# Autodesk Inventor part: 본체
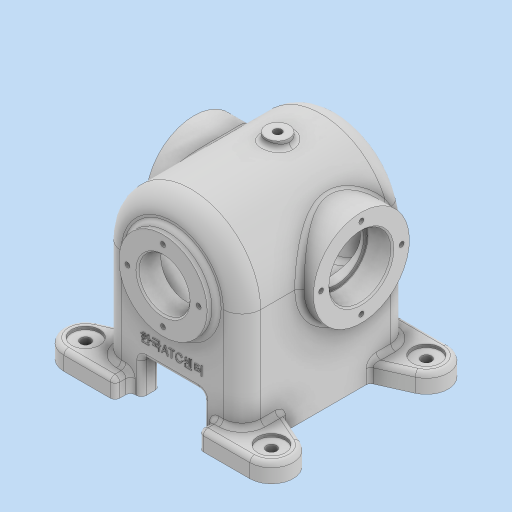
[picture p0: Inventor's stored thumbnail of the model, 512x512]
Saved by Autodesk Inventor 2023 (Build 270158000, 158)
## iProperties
Created: 2024-09
Part Number: 본체
Material: 일반
Document SubType Name: Modeling
Designer: asung
Density: 1 g/cm^3
Appearance: 기본값
Author: asung
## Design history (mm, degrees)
sketch "스케치1"
  geometry: L1 (-45, 0)-(45, 0); L2 (45, 0)-(45, -76); L3 (45, -76)-(-45, -76); L4 (-45, -76)-(-45, 0); L5 (-45, 0)-(45, -76); L6 (45, 0)-(-45, -76); L7 (-20, -53)-(20, -53); L8 (20, -53)-(20, -76); L9 (20, -76)-(-20, -76); L10 (-20, -76)-(-20, -53); L11 (-20, -53)-(20, -76); L12 (20, -53)-(-20, -76); C1 r 45 at (0, 0); 9 further points
  constraints: 24 end point, 7 midpoint, 4 parallel, 2 coincident, 2 horizontal, 2 perpendicular, 1 centre point
  dimensions: "d0" = 90 diameter of C1; "d2" = 90 distance of L2.end L3.end; "d3" = 76 distance of L1.end L2.end; "d4" = 40 distance of L8.end L9.end; "d5" = 23 distance of L7.end L8.end
extrude "돌출1" new body sketch "스케치1" stored distance "d6" = 108; taper "d7" = 0 deg
sketch "스케치2"
  geometry: C1 r 28.5 at (0, 0); 1 further point
  constraints: 1 centre point, 1 coincident
  dimensions: "d8" = 57 diameter of C1
extrude "돌출2" join sketch "스케치2" distance "d9" = 6; taper "d10" = 0 deg
node "작업 평면2"
sketch "스케치3"
  geometry: L1 (28.5, 60)-(-28.5, 60) reference; C1 r 31 at (0, -14); 2 further points
  constraints: 1 centre point, 1 midpoint, 1 vertical alignment
  dimensions: "d80" = 62 diameter of C1; "d81" = 74 distance from line of L1 C1.centre
extrude "돌출3" join sketch "스케치3" stored distance "d13" = 6; taper "d14" = 0 deg
sketch "스케치6"
  geometry: L1 (-28.5, 54)-(-28.5, 60) reference; L2 (-28.5, 60)-(28.5, 60) reference; L3 (28.5, 60)-(28.5, 54) reference; L4 (28.5, 54)-(45, 54) reference; L5 (45, 54)-(45, -54) reference; L6 (45, -54)-(-53, -54) reference; L7 (-53, -54)-(-53, 54) reference; L8 (-53, 54)-(-28.5, 54) reference; L9 (0, -54)-(0, 54) reference; L10 (0, -54)-(0, 60); L11 (28.5, 60)-(-28.5, 60) reference; L12 (0, -45)-(33, -45); L13 (36, -42)-(36, 42); L14 (33, 45)-(0, 45); L15 (0, 45)-(0, -45); A1 r 3 centre (33, -42) between (33, -45) and (36, -42); A2 r 3 centre (33, 42) between (36, 42) and (33, 45); 5 further points
  constraints: 10 end point, 4 point on circle, 4 tangent, 2 centre point, 2 parallel, 1 equal radius, 1 horizontal, 1 midpoint, 1 perpendicular, 1 point on line
  dimensions: "d29" = 9 distance between parallel lines of L13 L5; "d30" = 9 distance between parallel lines of L12 L6; "d31" = 9 distance between parallel lines of L4 L14; "d32" = 3 radius of A1
revolve "회전1" sketch "스케치6" stored, may be unused: angle "d33" = 90 deg
sketch "스케치7"
  geometry: C1 r 28.5 at (0, 0) reference; 2 further points
  constraints: 1 coincident
hole "구멍3" sketch "스케치7" at (0, 0) diameter "d34" = 33; stored, may be unused: countersink angle "d38" = 90 deg, drill point angle "d40" = 118 deg; dims "d35" = 6, "d36" = 40, "d37" = 16, "d39" = 60
chamfer "모따기1" distance "d41" = 1; stored, may be unused: second distance "d42" = 2, angle "d43" = 45 deg
fillet "모깎기1" dims "d44" = 12
node "작업 평면3"
sketch "스케치11" dims "d69" = 46
  geometry: C1 r 16.5 at (0, 0) reference; 3 further points
  constraints: 2 vertical alignment, 1 coincident, 2 other
hole "구멍6" sketch "스케치11" at (0, 23) diameter "d70" = 3.242; stored, may be unused: countersink angle "d74" = 90 deg, drill point angle "d76" = 118 deg; dims "d71" = 8, "d72" = 4, "d73" = 2, "d75" = 10
sketch "스케치12"
  geometry: C1 r 31 at (0, 0) reference; 2 further points
  constraints: 1 coincident
hole "구멍7" sketch "스케치12" at (0, 0) diameter "d82" = 35; stored, may be unused: countersink angle "d86" = 90 deg, drill point angle "d88" = 118 deg; dims "d83" = 8, "d84" = 40, "d85" = 16, "d87" = 100
sketch "스케치13"
  geometry: C1 r 31 at (0, 0) reference; 2 further points
  constraints: 1 coincident
hole "구멍8" sketch "스케치13" at (0, 0) diameter "d89" = 35; stored, may be unused: countersink angle "d93" = 90 deg, drill point angle "d95" = 118 deg; dims "d90" = 6, "d91" = 40, "d92" = 16, "d94" = 100
chamfer "모따기2" distance "d96" = 1; stored, may be unused: second distance "d97" = 2, angle "d98" = 45 deg
fillet "모깎기4" dims "d99" = 0.3
fillet "모깎기5" dims "d100" = 3
node "작업 평면5"
sketch "스케치14"
  geometry: L1 (48.5, 114)-(-8.5, 114) reference; L2 (74, 9)-(74, 71) reference; C1 r 7.5 at (20, 40); 2 further points
  constraints: 1 centre point, 1 midpoint, 1 vertical alignment
  dimensions: "d102" = 15 diameter of C1; "d103" = 74 distance from line of L1 C1.centre
extrude "돌출5" join sketch "스케치14" stored distance "d104" = 10; taper "d105" = 0 deg
fillet "모깎기6" dims "d110" = 3
sketch "스케치16"
  geometry: C1 r 7.5 at (0, 0) reference; 2 further points
  constraints: 1 coincident
hole "구멍9" sketch "스케치16" at (0, 0) diameter "d111" = 5.1881; stored, may be unused: countersink angle "d115" = 90 deg, drill point angle "d117" = 118 deg; dims "d112" = 20, "d113" = 40, "d114" = 16, "d116" = 21
sketch "스케치18" dims "d125" = 52
  geometry: C1 r 31 at (0, 0) reference; C2 r 21 at (0, 0) reference; 3 further points
  constraints: 2 vertical alignment, 1 coincident, 2 other
hole "구멍11" sketch "스케치18" at (0, 26) diameter "d126" = 3.242; stored, may be unused: countersink angle "d130" = 90 deg, drill point angle "d132" = 118 deg; dims "d127" = 8, "d128" = 4, "d129" = 2, "d131" = 10
sketch "스케치19"
  geometry: L1 (0, 0)-(-13, 0) reference; L2 (0, 0)-(0, 108) reference; L3 (-13, 108)-(0, 108) reference; L4 (-25, 96)-(-25, 12) reference; L5 (65, 12)-(65, 96) reference; L6 (40, 108)-(53, 108) reference; L7 (40, 0)-(40, 108) reference; L8 (53, 0)-(40, 0) reference; L9 (-40, -10)-(-7, -10); L10 (-7, -10)-(-7, 0); L11 (-25, 26)-(-45.693, 16.79); L12 (-25, 54)-(65, 54); L13 (18.379, 114)-(21.621, 114) reference; L14 (40, 0)-(0, 0) reference; L15 (20, 0)-(20, 108); L16 (0, 108)-(40, 108) reference; L17 (20, 114)-(20, 108); L18 (21.621, 104)-(21.621, 114) reference; L19 (-7, 118)-(-7, 108); L20 (-40, 118)-(-7, 118); L21 (-25, 82)-(-45.693, 91.21); L22 (47, -10)-(47, 0); L23 (80, -10)-(47, -10); L24 (65, 26)-(85.693, 16.79); L25 (65, 82)-(85.693, 91.21); L26 (80, 118)-(47, 118); L27 (47, 118)-(47, 108); A1 r 12 centre (-13, 12) between (-25, 12) and (-13, 0) reference; A2 r 12 centre (-13, 96) between (-13, 108) and (-25, 96) reference; A3 r 12 centre (53, 12) between (53, 0) and (65, 12) reference; A4 r 12 centre (53, 96) between (65, 96) and (53, 108) reference; A5 r 14 centre (-40, 4) between (-40, -10) and (-45.693, 16.79); A6 r 14 centre (-40, 104) between (-40, 118) and (-45.693, 91.21); A7 r 14 centre (80, 4) between (80, -10) and (85.693, 16.79); A8 r 14 centre (80, 104) between (80, 118) and (85.693, 91.21); 7 further points
  constraints: 30 end point, 18 symmetric about line, 8 point on circle, 5 midpoint, 4 centre point, 2 point on line, 2 tangent, 1 horizontal, 1 parallel, 1 perpendicular, 3 other
  dimensions: "d136" = 28 diameter of A5; "d137" = 60 horizontal distance of point (20, 54) A5.centre; "d138" = 18 distance between parallel lines of L10 L4; "d139" = 36 vertical distance of L9.start L11.start; "d140" = 50 vertical distance of L12.start A5.centre; "d199" = 36 vertical distance of L20.start L21.start (derived); "d200" = 36 vertical distance of L24.start L23.start (derived); "d201" = 36 vertical distance of L26.start L25.start (derived)
extrude "돌출7" join sketch "스케치19" distance "d141" = 12; taper "d142" = 0 deg
fillet "모깎기7" dims "d143" = 3
sketch "스케치21"
  geometry: L1 (-7, -7)-(-7, -3) reference; L2 (0, 0)-(-4, 0) reference; L3 (0, 0)-(0, 108) reference; L4 (-4, 108)-(0, 108) reference; L5 (-7, 111)-(-7, 115) reference; L6 (-10, 118)-(-40, 118) reference; L7 (-45.693, 91.21)-(-25, 82) reference; L8 (-25, 82)-(-25, 27.949) reference; L9 (-26.78, 25.208)-(-45.693, 16.79) reference; L10 (-40, -10)-(-10, -10) reference; L11 (56, 96)-(56, 12) reference; L12 (50, -10)-(80, -10) reference; L13 (85.693, 16.79)-(66.78, 25.208) reference; L14 (65, 27.949)-(65, 80.051) reference; L15 (66.78, 82.792)-(85.693, 91.21) reference; L16 (80, 118)-(50, 118) reference; L17 (47, 115)-(47, 111) reference; L18 (40, 108)-(44, 108) reference; L19 (40, 0)-(40, 108) reference; L20 (44, 0)-(40, 0) reference; L21 (47, -3)-(47, -7) reference; L22 (53, 9)-(-13, 9); L23 (-16, 12)-(-16, 96); L24 (-13, 99)-(53, 99); L25 (56, 96)-(56, 12); L26 (56, 9)-(-16, 99); L27 (-16, 9)-(56, 99); A1 r 3 centre (-10, -7) between (-10, -10) and (-7, -7) reference; A2 r 3 centre (-4, -3) between (-4, 0) and (-7, -3) reference; A3 r 3 centre (-4, 111) between (-7, 111) and (-4, 108) reference; A4 r 3 centre (-10, 115) between (-7, 115) and (-10, 118) reference; A5 r 14 centre (-40, 104) between (-40, 118) and (-45.693, 91.21) reference; A6 r 3 centre (-28, 27.949) between (-26.78, 25.208) and (-25, 27.949) reference; A7 r 14 centre (-40, 4) between (-45.693, 16.79) and (-40, -10) reference; A8 r 3 centre (50, -7) between (47, -7) and (50, -10) reference; A9 r 14 centre (80, 4) between (80, -10) and (85.693, 16.79) reference; A10 r 3 centre (68, 27.949) between (65, 27.949) and (66.78, 25.208) reference; A11 r 3 centre (68, 80.051) between (66.78, 82.792) and (65, 80.051) reference; A12 r 14 centre (80, 104) between (85.693, 91.21) and (80, 118) reference; A13 r 3 centre (50, 115) between (50, 118) and (47, 115) reference; A14 r 3 centre (44, 111) between (44, 108) and (47, 111) reference; A15 r 3 centre (44, -3) between (47, -3) and (44, 0) reference; A16 r 3 centre (-13, 12) between (-16, 12) and (-13, 9); A17 r 3 centre (-13, 96) between (-13, 99) and (-16, 96); A18 r 3 centre (53, 12) between (53, 9) and (56, 12); A19 r 3 centre (53, 96) between (56, 96) and (53, 99); 4 further points
  constraints: 12 end point, 8 point on circle, 8 point on line, 8 tangent, 4 centre point, 3 equal radius, 2 midpoint, 2 parallel, 1 horizontal, 1 perpendicular
  dimensions: "d149" = 9 distance between parallel lines of L8 L23; "d150" = 9 distance between parallel lines of L14 L25; "d151" = 9 distance between parallel lines of L4 L24; "d152" = 9 distance between parallel lines of L22 L2; "d153" = 3 radius of A16 (derived)
  node "투영된 루프4"
  node "투영된 루프5"
sketch "스케치22"
  geometry: L1 (38.3, -14.283)-(53, -14.283) reference; L2 (54, -15.652)-(54, -27.659) reference; L3 (54, -27.659)-(48, -27.659) reference; L4 (45, -30.984)-(45, -76) reference; L5 (45, -76)-(20, -76) reference; L6 (-20, -76)-(-45, -76) reference; L7 (-45, -76)-(-45, -30.984) reference; L8 (-48, -27.659)-(-54, -27.659) reference; L9 (-54, -27.659)-(-54, -15.652) reference; L10 (-53, -14.283)-(-38.3, -14.283) reference; L11 (-38, -13.86)-(-38, -10.5) reference; L12 (-38, -10.5)-(-34.435, -10.5) reference; L13 (34.435, -10.5)-(38, -10.5) reference; L14 (38, -10.5)-(38, -13.86) reference; L15 (38, 13.86)-(38, 10.5) reference; L16 (38, 10.5)-(34.435, 10.5) reference; L17 (-34.435, 10.5)-(-38, 10.5) reference; L18 (-38, 10.5)-(-38, 13.86) reference; L19 (-38.3, 14.283)-(-53, 14.283) reference; L20 (-54, 15.652)-(-54, 27.659) reference; L21 (-54, 27.659)-(-37.199, 27.659) reference; L22 (37.199, 27.659)-(54, 27.659) reference; L23 (54, 27.659)-(54, 15.652) reference; L24 (53, 14.283)-(38.3, 14.283) reference; L25 (-36, -45)-(-36, -27); L26 (20, -76)-(20, -53) reference; L27 (20, -53)-(-20, -53) reference; L28 (-20, -53)-(-20, -76) reference; L29 (-36, -45)-(-36, -76); L30 (-60, -76)-(-30, -76) reference; L31 (30, -76)-(60, -76) reference; L32 (36, -76)-(36, -27); L33 (36, -76)-(89.801, -76); A1 r 36 centre (0, 0) between (-34.435, -10.5) and (34.435, -10.5) reference; A2 r 36 centre (0, 0) between (34.435, 10.5) and (-34.435, 10.5) reference; A3 r 45 centre (0, 0) between (34.369, 29.047) and (-34.369, 29.047) reference; A4 r 45 centre (0, 0) between (-36, -27) and (36, -27); 5 further points
  constraints: 8 end point, 2 point on circle, 2 point on line, 1 centre point, 1 coincident, 1 horizontal, 1 perpendicular, 1 vertical, 12 other
  dimensions: "d156" = 90 diameter of A4; "d162" = 9 distance between parallel lines of L4 L32
extrude "돌출11" cut sketch "스케치22" stored distance "d163" = 84; taper "d164" = 0 deg
node "작업 평면6"
node "작업 평면7"
node "작업 평면8"
sketch "스케치24"
  geometry: L1 (28.5, 60)-(-28.5, 60) reference; C1 r 7.5 at (0, -14); 2 further points
  constraints: 1 centre point, 1 midpoint, 1 vertical alignment
  dimensions: "d169" = 15 diameter of C1; "d170" = 74 distance from line of L1 C1.centre
extrude "돌출12" join sketch "스케치24" stored distance "d171" = 10; taper "d172" = 0 deg
fillet "모깎기9" dims "d173" = 3
sketch "스케치25"
  geometry: C1 r 7.5 at (0, 0) reference; 2 further points
  constraints: 1 coincident
hole "구멍12" sketch "스케치25" at (0, 0) diameter "d174" = 5.1881; stored, may be unused: countersink angle "d178" = 90 deg, drill point angle "d180" = 118 deg; dims "d175" = 20, "d176" = 4, "d177" = 2, "d179" = 21
fillet "모깎기10" dims "d181" = 3
fillet "모깎기11" dims "d182" = 3
fillet "모깎기14" dims "d185" = 3
fillet "모깎기15" dims "d186" = 3
fillet "모깎기16" dims "d187" = 3
sketch "스케치26"
  geometry: A1 r 11 centre (80, -104) between (80, -115) and (84.473, -93.95) reference; A2 r 11 centre (80, -4) between (84.473, -14.05) and (80, 7) reference; A3 r 11 centre (-40, -104) between (-44.473, -93.95) and (-40, -115) reference; A4 r 14 centre (-40, -4) between (-40, 10) and (-45.693, -16.79) reference; 5 further points
  constraints: 4 coincident
hole "구멍13" sketch "스케치26" at (80, -104), (80, -4), (-40, -104), (-40, -4) diameter "d188" = 6.6; stored, may be unused: countersink angle "d192" = 90 deg, drill point angle "d194" = 118 deg; dims "d189" = 20, "d190" = 18, "d191" = 2, "d193" = 21
fillet "모깎기17" dims "d195" = 3
sketch "스케치27"
  geometry: L1 (60, -76)-(74, -76) reference; L2 (-17, -53)-(17, -53) reference; 4 further points
  constraints: 1 midpoint, 1 vertical alignment, 1 other
  dimensions: "d196" = 35 distance from line of L1 point (0, -41)
feature "엠보싱1" sketch "스케치27" dims "d197" = 0.5, "d198" = 0
node "솔리드1"
pattern_circular "원형 패턴2" dims angle "d78" = 360 deg
mirror "미러3"
pattern_circular "원형 패턴3" dims angle "d134" = 360 deg
mirror "미러4"
node "투영된 루프1"
node "투영된 루프2"
node "투영된 루프3"
node "절단 모서리 투영1"
node "절단 모서리 투영3"
feature "A9D066F2-1C7D-4E18-AEED-F7BC21143FA4" dims "d34" = 33, "d35" = 6, "d36" = 40, "d37" = 16, "d38" = 90 deg, "d39" = 60, "d40" = 118 deg
other parameters: "d11" = 54, "d57" = -125, "d101" = -125, "d165" = 4, "d168" = -4
